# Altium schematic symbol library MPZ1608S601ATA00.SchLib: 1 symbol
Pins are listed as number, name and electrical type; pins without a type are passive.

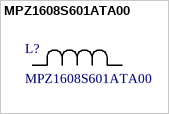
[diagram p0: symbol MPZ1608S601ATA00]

## MPZ1608S601ATA00
designator L?
INDUCTOR; SMT (0603); FERRITE-BEAD; 600; TOL=+/-25%; 1A; -55 DEGC TO +125 DEGC; Manufacturer_Name: TDK
footprint IND_1608_TDK
pins: 1, 2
